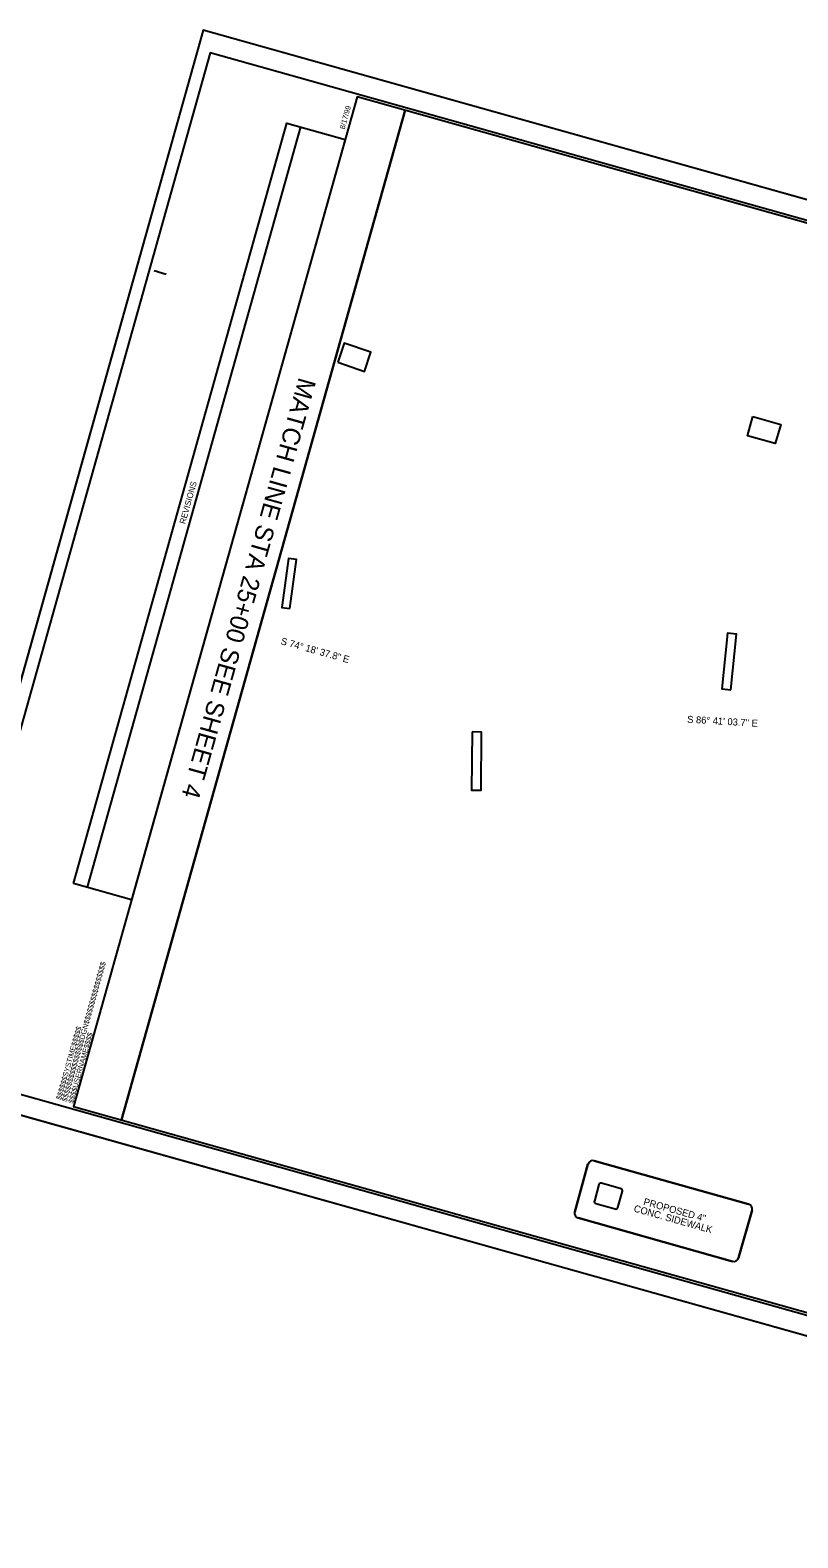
# Model space of a CAD drawing. Extents: x 928111 to 937215, y 684320 to 686530.
# Drawn here: x 929113 to 929882, y 684943 to 686453 of the extents above; entities that cross this region are included whole.
import ezdxf

# ---------------------------------------------------------------- set-up
doc = ezdxf.new("R2010")
doc.units = 0
for name, color, linetype in [('Exist Horizontal Alignment Direction Label', 7, 'Continuous'), ('Matchline', 7, 'Continuous'), ('Matchline Text', 7, 'Continuous'), ('Old_Level_2', 7, 'Continuous'), ('Prop DSN Text', 7, 'Continuous'), ('Sheet Cutting Line CELL', 7, 'Continuous'), ('Sheet Layout Plan Border', 7, 'Continuous'), ('Sheet Plan CELL', 7, 'Continuous'), ('Sheet Plan Layout CELL', 7, 'Continuous'), ('Sheet Plot Border Inside CELL', 7, 'Continuous'), ('Sheet Plot Border Outside CELL', 7, 'Continuous')]:
    doc.layers.add(name, color=color, linetype=linetype)

msp = doc.modelspace()

# ---------------------------------------------------------------- linework, layer by layer
at = {"layer": 'Matchline'}
msp.add_line((929205, 685361.8), (929488.9, 686372.6), dxfattribs=at)
at = {"layer": 'Old_Level_2'}
for p, q in [((929683, 685297), (929678.4, 685280.6)), ((929705.1, 685292.9), (929685.5, 685298.4)), ((929701.9, 685274), (929706.5, 685290.4)), ((929679.8, 685278.2), (929699.4, 685272.7))]:
    msp.add_line(p, q, dxfattribs=at)
for centre, start, end in [((929684.9, 685296.5), 74.3105, 164.3105), ((929680.3, 685280.1), 164.3105, 254.3105), ((929704.5, 685291), 344.3105, 74.3105), ((929699.9, 685274.6), 254.3105, 344.3105)]:
    msp.add_arc(centre, 2, start, end, dxfattribs=at)
at = {"layer": 'Prop DSN Text'}
for p, q in [((929672, 685317.5), (929658.7, 685269.8)), ((929658.7, 685269.8), (929672, 685317.5)), ((929832.8, 685277.5), (929678.2, 685320.9)), ((929678.2, 685320.9), (929832.8, 685277.5)), ((929822.9, 685223.7), (929836.3, 685271.3)), ((929836.3, 685271.3), (929822.9, 685223.7)), ((929662.1, 685263.7), (929816.8, 685220.2)), ((929816.8, 685220.2), (929662.1, 685263.7))]:
    msp.add_line(p, q, dxfattribs=at)
for points in [[(929421.4, 686120.3), (929448.2, 686111.2), (929454.7, 686130.5), (929427.9, 686139.6)], [(929837.1, 686066.1), (929865, 686058.2), (929859.6, 686038.9), (929831.7, 686046.7)], [(929373.5, 685873.8), (929380.2, 685922.8), (929372.1, 685923.9), (929365.4, 685874.9)], [(929815.2, 685792.5), (929820.9, 685848.1), (929811.7, 685849), (929806.1, 685793.5)], [(929555.9, 685750.2), (929555.3, 685692), (929564.9, 685691.9), (929565.4, 685750.1)]]:
    msp.add_lwpolyline(points, close=True, dxfattribs=at)
for centre, start, end in [((929676.9, 685316.1), 74.3105, 164.3105), ((929676.9, 685316.1), 74.3105, 164.3105), ((929663.5, 685268.5), 164.3105, 254.3105), ((929663.5, 685268.5), 164.3105, 254.3105), ((929831.5, 685272.7), 344.3105, 74.3105), ((929831.5, 685272.7), 344.3105, 74.3105), ((929818.1, 685225.1), 254.3105, 344.3105), ((929818.1, 685225.1), 254.3105, 344.3105)]:
    msp.add_arc(centre, 5, start, end, dxfattribs=at)
at = {"layer": 'Sheet Cutting Line CELL'}
for p, q in [((929286.6, 686452.8), (928990.5, 685398.6)), ((930907.4, 685997.6), (929286.6, 686452.8)), ((928990.5, 685398.6), (930611.3, 684943.4))]:
    msp.add_line(p, q, dxfattribs=at)
at = {"layer": 'Sheet Layout Plan Border'}
msp.add_line((929488.9, 686372.7), (929205, 685361.8), dxfattribs=at)
at = {"layer": 'Sheet Plan CELL'}
for p, q in [((929440.8, 686386.2), (929440.8, 686386.2)), ((929170.7, 685594.7), (929384.5, 686355.9)), ((929237.7, 686212.1), (929249.7, 686208.7)), ((929156.9, 685375.3), (929156.9, 685375.3))]:
    msp.add_line(p, q, dxfattribs=at)
for points in [[(930884.9, 685980.5), (929440.8, 686386.2), (929156.9, 685375.3), (930601, 684969.7)], [(929156.7, 685598.6), (929370.5, 686359.8), (929428.8, 686343.5), (929215, 685582.3)]]:
    msp.add_lwpolyline(points, close=True, dxfattribs=at)
at = {"layer": 'Sheet Plan Layout CELL'}
msp.add_lwpolyline([(929440.8, 686386.2), (929156.9, 685375.3), (930601, 684969.7), (930827.7, 685776.9), (930597.4, 685841.6), (930654.6, 686045.2)], close=True, dxfattribs=at)
at = {"layer": 'Sheet Plot Border Inside CELL'}
msp.add_lwpolyline([(929008.4, 685414.4), (930612.3, 684963.9), (930897.6, 685979.6), (929293.7, 686430.1)], close=True, dxfattribs=at)
at = {"layer": 'Sheet Plot Border Outside CELL'}
msp.add_lwpolyline([(928990.5, 685398.6), (930611.3, 684943.4), (930907.4, 685997.6), (929286.6, 686452.8)], close=True, dxfattribs=at)

# ---------------------------------------------------------------- texts
at = {"layer": 'Exist Horizontal Alignment Direction Label'}
for s, rotation, p in [('S 74%%d 18\' 37.8" E', 344.3105, (929363.8, 685838.2)), ('S 86%%d 41\' 03.7" E', 356.6844, (929771.2, 685759.5))]:
    msp.add_text(s, height=7, rotation=rotation, dxfattribs=at).set_placement(p)
at = {"layer": 'Matchline Text'}
msp.add_text('MATCH LINE STA 25+00 SEE SHEET 4 ', height=18, rotation=254.3105, dxfattribs=at).set_placement((929382.6, 686106))
at = {"layer": 'Prop DSN Text'}
for s, p in [('PROPOSED 4"', (929727, 685277)), ('CONC. SIDEWALK', (929717.3, 685270.2))]:
    msp.add_text(s, height=7, rotation=344.3105, dxfattribs=at).set_placement(p)
at = {"layer": 'Sheet Plan CELL'}
for s, height, p in [('8/17/99', 5.25, (929428.2, 686353.1)), ('REVISIONS', 6, (929268.6, 685958)), ('$$$$$$$$$$$$$$$$DGN$$$$$$$$$$$$$$$$', 5.25, (929150.1, 685379.6)), ('$$$$$$SYSTIME$$$$$', 5.25, (929144.3, 685381.3)), ('$$$$USERNAME$$$$', 5.25, (929156.4, 685377.9))]:
    msp.add_text(s, height=height, rotation=74.3105, dxfattribs=at).set_placement(p)

doc.saveas('drawing.dxf')
